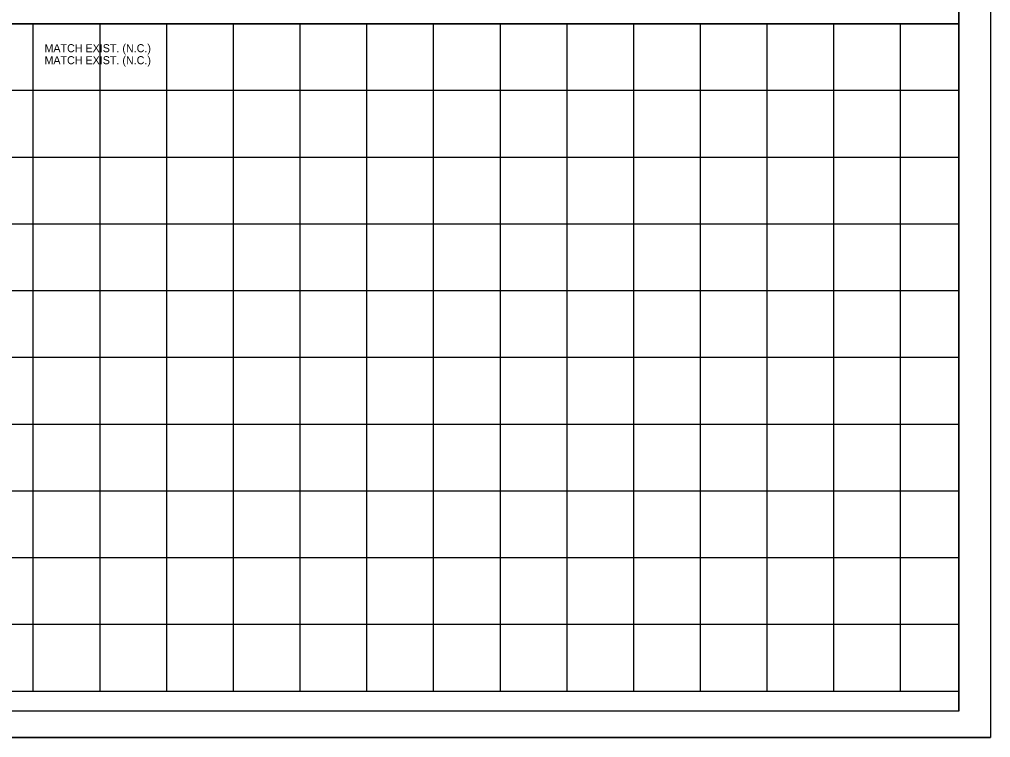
# Model space of a CAD drawing. Extents: x 816090 to 819714, y 1801340 to 1803641.
# Drawn here: x 817029 to 817757, y 1802574 to 1803112 of the extents above; entities that cross this region are included whole.
import ezdxf

# ---------------------------------------------------------------- set-up
doc = ezdxf.new("R2010")
doc.units = 0
for name, color, linetype in [('R_Border', 7, 'Continuous'), ('R_Horz Alg Annot', 7, 'Continuous'), ('R_No Plot', 7, 'Continuous')]:
    doc.layers.add(name, color=color, linetype=linetype)

msp = doc.modelspace()

# ---------------------------------------------------------------- linework, layer by layer
at = {"layer": 'R_Border'}
for p, q in [((817732.96, 1802593.83), (817732.96, 1803621.13)), ((817732.96, 1803108.53), (816152.06, 1803108.53)), ((817039.36, 1802608.53), (817039.36, 1803108.53)), ((817089.36, 1802608.53), (817089.36, 1803108.53)), ((817139.36, 1802608.53), (817139.36, 1803108.53)), ((817189.36, 1802608.53), (817189.36, 1803108.53)), ((817239.36, 1802608.53), (817239.36, 1803108.53)), ((817289.36, 1802608.53), (817289.36, 1803108.53)), ((817339.36, 1802608.53), (817339.36, 1803108.53)), ((817389.36, 1802608.53), (817389.36, 1803108.53)), ((817439.36, 1802608.53), (817439.36, 1803108.53)), ((817489.36, 1802608.53), (817489.36, 1803108.53)), ((817539.36, 1802608.53), (817539.36, 1803108.53)), ((817589.36, 1802608.53), (817589.36, 1803108.53)), ((817639.36, 1802608.53), (817639.36, 1803108.53)), ((817689.36, 1802608.53), (817689.36, 1803108.53)), ((817732.96, 1803058.53), (816152.06, 1803058.53)), ((817732.96, 1803008.53), (816152.06, 1803008.53)), ((817732.96, 1802958.53), (816152.06, 1802958.53)), ((817732.96, 1802908.53), (816152.06, 1802908.53)), ((817732.96, 1802858.53), (816152.06, 1802858.53)), ((817732.96, 1802808.53), (816152.06, 1802808.53)), ((817732.96, 1802758.53), (816152.06, 1802758.53)), ((817732.96, 1802708.53), (816152.06, 1802708.53)), ((817732.96, 1802658.53), (816152.06, 1802658.53)), ((817732.96, 1802608.53), (816152.06, 1802608.53)), ((817732.96, 1802593.83), (816152.06, 1802593.83))]:
    msp.add_line(p, q, dxfattribs=at)
at = {"layer": 'R_No Plot'}
msp.add_line((816090.06, 1802573.94), (817756.73, 1802573.94), dxfattribs=at)
for points in [[(816090.06, 1803640.62), (817756.76, 1803640.62), (817756.76, 1802573.94), (816090.06, 1802573.94)], [(817419.76, 1803621.13), (817419.76, 1803571.73), (817500.32, 1803571.73), (817618.87, 1803571.73), (817618.87, 1803461.73), (817732.96, 1803461.73), (817732.96, 1803108.53), (816152.06, 1803108.53), (816152.06, 1803621.13)], [(816152.06, 1803108.53), (817732.96, 1803108.53), (817732.96, 1802593.83), (816152.06, 1802593.83)], [(816152.06, 1803108.53), (817732.96, 1803108.53), (817732.96, 1802593.83), (816152.06, 1802593.83)]]:
    msp.add_lwpolyline(points, close=True, dxfattribs=at)

# ---------------------------------------------------------------- texts
at = {"layer": 'R_Horz Alg Annot'}
for p in [(817047.72, 1803087.28), (817047.72, 1803078.28)]:
    msp.add_text('MATCH EXIST. (N.C.)', height=6, dxfattribs=at).set_placement(p)

doc.saveas('drawing.dxf')
